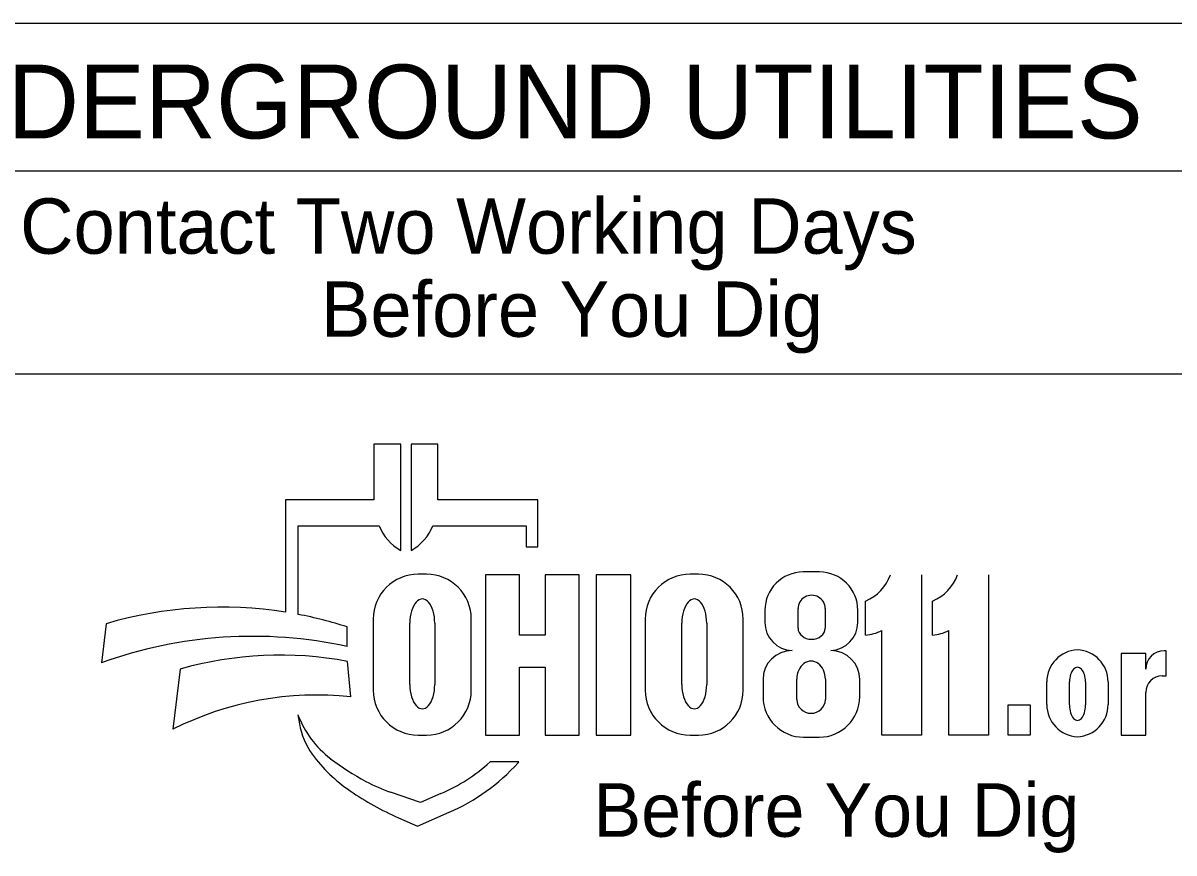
# Model space of a CAD drawing. Extents: x 0 to 34, y 0 to 22.
# Drawn here: x 27.662 to 31.093, y 12.841 to 15.314 of the extents above; entities that cross this region are included whole.
import ezdxf

# ---------------------------------------------------------------- set-up
doc = ezdxf.new("R2010")
doc.units = 0
doc.layers.add('SH_Data', color=7, linetype='Continuous')

msp = doc.modelspace()

# ---------------------------------------------------------------- linework, layer by layer
at = {"layer": 'SH_Data'}
for p, q in [((27.0189, 15.314), (32.2439, 15.314)), ((27.0189, 14.874), (32.2439, 14.874)), ((27.0189, 14.269), (32.2439, 14.269)), ((28.7879, 14.0595), (28.7078, 14.0595)), ((28.7078, 14.0595), (28.7078, 13.8929)), ((28.7879, 13.7427), (28.7879, 14.0595)), ((28.8991, 14.0595), (28.819, 14.0595)), ((28.819, 14.0595), (28.819, 13.7427)), ((28.8991, 13.8929), (28.8991, 14.0595)), ((28.7078, 13.8929), (28.4449, 13.8929)), ((28.4449, 13.8929), (28.4449, 13.5585)), ((29.1967, 13.8929), (28.8991, 13.8929)), ((29.1967, 13.7528), (29.1967, 13.8929)), ((28.4826, 13.5519), (28.4826, 13.8161)), ((28.4826, 13.8161), (28.7233, 13.8161)), ((28.8835, 13.8161), (29.1619, 13.8161)), ((29.1619, 13.8161), (29.1619, 13.7528)), ((29.1619, 13.7528), (29.1967, 13.7528)), ((28.8646, 13.6717), (28.8399, 13.6717)), ((29.1425, 13.6702), (29.041, 13.6702)), ((29.041, 13.6702), (29.041, 13.1923)), ((29.6753, 13.6717), (29.6506, 13.6717)), ((30.0365, 13.6783), (29.9876, 13.6783)), ((30.3402, 13.6702), (30.3402, 13.1923)), ((30.5403, 13.6702), (30.5403, 13.1923)), ((30.1735, 13.4899), (30.1735, 13.5918)), ((30.3736, 13.4899), (30.3736, 13.5918)), ((29.8736, 13.5643), (29.8736, 13.528)), ((29.9724, 13.511), (29.9724, 13.5697)), ((30.0533, 13.5697), (30.0533, 13.511)), ((30.1505, 13.528), (30.1505, 13.5643)), ((27.9098, 13.5243), (27.8958, 13.4076)), ((28.7062, 13.5381), (28.7062, 13.3259)), ((28.8151, 13.3429), (28.8151, 13.5257)), ((28.8895, 13.5257), (28.8895, 13.3429)), ((28.9982, 13.3259), (28.9982, 13.5381)), ((29.517, 13.5381), (29.517, 13.3259)), ((29.6259, 13.3429), (29.6259, 13.5257)), ((29.7003, 13.5257), (29.7003, 13.3429)), ((29.809, 13.3259), (29.809, 13.5381)), ((28.6288, 13.4566), (28.6288, 13.5146)), ((30.2217, 13.1923), (30.2217, 13.5039)), ((30.4219, 13.1923), (30.4219, 13.5039)), ((31.009, 13.4357), (30.936, 13.4357)), ((30.936, 13.4357), (30.936, 13.1923)), ((31.009, 13.3886), (31.009, 13.4357)), ((31.0697, 13.4434), (31.0638, 13.4434)), ((31.0697, 13.3689), (31.0697, 13.4434)), ((28.1305, 13.389), (28.1085, 13.2096)), ((28.6389, 13.3061), (28.6296, 13.4121)), ((29.1425, 13.1923), (29.1425, 13.3943)), ((29.868, 13.3578), (29.868, 13.307)), ((29.9688, 13.2981), (29.9688, 13.3592)), ((30.0538, 13.3592), (30.0538, 13.2981)), ((30.1565, 13.307), (30.1565, 13.3578)), ((30.7141, 13.2831), (30.7141, 13.3509)), ((30.7813, 13.282), (30.7813, 13.3509)), ((30.8294, 13.3509), (30.8294, 13.282)), ((30.8966, 13.3509), (30.8966, 13.2831)), ((31.0583, 13.3689), (31.0697, 13.3689)), ((31.009, 13.1923), (31.009, 13.3196)), ((28.4816, 13.2524), (28.4862, 13.2256)), ((28.8399, 13.1923), (28.8646, 13.1923)), ((29.041, 13.1923), (29.1425, 13.1923)), ((29.6506, 13.1923), (29.6753, 13.1923)), ((29.989, 13.1861), (30.0356, 13.1861)), ((30.3402, 13.1923), (30.2217, 13.1923)), ((30.5403, 13.1923), (30.4219, 13.1923)), ((30.936, 13.1923), (31.009, 13.1923)), ((29.1401, 13.1123), (29.0543, 13.1123)), ((29.1377, 13.1096), (29.1401, 13.1123)), ((28.8466, 12.9915), (28.7579, 13.0221)), ((28.9079, 13.0181), (28.8466, 12.9915)), ((28.7818, 12.9458), (28.8376, 12.9212)), ((28.8376, 12.9212), (28.9322, 12.9623))]:
    msp.add_line(p, q, dxfattribs=at)
for points in [[(29.1425, 13.3943), (29.2186, 13.3943), (29.2186, 13.1923), (29.3201, 13.1923), (29.3201, 13.6702), (29.2186, 13.6702), (29.2186, 13.4899), (29.1425, 13.4899), (29.1425, 13.6702)], [(29.3709, 13.1923), (29.4736, 13.1923), (29.4736, 13.6702), (29.3709, 13.6702), (29.3709, 13.1923)], [(29.9545, 13.4444), (29.9545, 13.4443)], [(30.07, 13.4443), (30.07, 13.4444)]]:
    msp.add_lwpolyline(points, dxfattribs=at)
msp.add_lwpolyline([(30.5983, 13.282), (30.6642, 13.282), (30.6642, 13.1923), (30.5983, 13.1923)], close=True, dxfattribs=at)
for centre, radius, start, end in [((28.8598, 13.871), 0.1471, 201.9296, 240.7469), ((28.7471, 13.871), 0.1471, 299.2531, 338.0704), ((28.8399, 13.5381), 0.1337, 90, 180), ((28.8646, 13.5381), 0.1337, 0, 90), ((29.6506, 13.5381), 0.1337, 90, 180), ((29.6753, 13.5381), 0.1337, 0, 90), ((29.9876, 13.5643), 0.114, 90, 180), ((30.0365, 13.5643), 0.114, 0, 90), ((30.1228, 13.7139), 0.1322, 292.5572, 340.7355), ((30.3229, 13.7139), 0.1322, 292.5572, 340.7355), ((28.2535, 12.35), 1.2235, 81.0007, 106.3144), ((28.2535, 12.35), 1.2235, 72.1402, 79.2074), ((29.9572, 13.528), 0.0837, 180, 268.1442), ((30.0668, 13.528), 0.0837, 272.2058, 0), ((28.3477, 12.1542), 1.3324, 77.8238, 109.8274), ((30.1615, 13.6216), 0.1322, 275.1733, 297.0931), ((30.3617, 13.6216), 0.1322, 275.1733, 297.0931), ((28.4291, 12.3369), 1.0937, 79.44, 105.8467), ((29.9545, 13.3578), 0.0865, 90, 180), ((30.07, 13.3578), 0.0865, 0, 90), ((30.8096, 13.3509), 0.0956, 92.5886, 180), ((30.801, 13.3509), 0.0956, 0, 87.4114), ((31.0638, 13.3886), 0.0548, 90, 180), ((31.0583, 13.3196), 0.0493, 90, 180), ((28.8399, 13.3259), 0.1337, 180, 270), ((28.8646, 13.3259), 0.1337, 270, 0), ((29.6506, 13.3259), 0.1337, 180, 270), ((29.6753, 13.3259), 0.1337, 270, 0), ((28.5367, 12.362), 0.9496, 83.8248, 116.8021), ((29.989, 13.307), 0.1209, 180, 270), ((30.0356, 13.307), 0.1209, 270, 0), ((30.8096, 13.2831), 0.0956, 180, 267.4114), ((30.801, 13.2831), 0.0956, 272.5886, 0), ((28.7616, 13.3601), 0.2999, 201.0457, 232.5314), ((28.6973, 13.2616), 0.2141, 189.6817, 216.0884), ((28.897, 13.4072), 0.4612, 216.0884, 235.7167), ((29.0492, 13.7354), 0.7728, 232.5314, 241.794), ((28.6937, 13.5117), 0.5381, 293.4582, 312.0712), ((28.6937, 13.5117), 0.599, 293.4582, 317.8286), ((28.922, 13.4981), 0.5035, 241.794, 250.9821), ((29.1457, 13.7721), 0.9028, 235.7167, 246.2325)]:
    msp.add_arc(centre, radius, start, end, dxfattribs=at)
for centre, major_axis, ratio, start_param, end_param in [((28.8523, 13.5257), (0, 0.0723), 0.514403, 4.712389, 7.853982), ((29.6631, 13.5257), (0, 0.0723), 0.514403, 4.712389, 7.853982), ((30.0128, 13.5697), (0.0404, 0), 0.969373, 0, 3.141593), ((30.0128, 13.511), (0.0404, 0), 0.818453, 3.141593, 6.283185), ((30.0113, 13.3592), (0, 0.0535), 0.794529, 4.712389, 7.853982), ((30.8053, 13.3509), (0, 0.0434), 0.553236, 4.712389, 7.853982), ((28.8523, 13.3429), (0, 0.0723), 0.514403, 1.570796, 4.712389), ((29.6631, 13.3429), (0, 0.0723), 0.514403, 1.570796, 4.712389), ((30.0113, 13.2981), (0.0425, 0), 0.959837, 3.141593, 6.283185), ((30.8053, 13.282), (0, 0.046), 0.522014, 1.570796, 4.712389)]:
    msp.add_ellipse(centre, major_axis=major_axis, ratio=ratio, start_param=start_param, end_param=end_param, dxfattribs=at)

# ---------------------------------------------------------------- texts
for s, height, p in [('UNDERGROUND UTILITIES', 0.22, (27.1915, 14.9701)), ('Contact Two Working Days', 0.165, (27.6533, 14.6266)), ('Before You Dig', 0.165, (28.5505, 14.3791)), ('Before You Dig', 0.15972, (29.3624, 12.8893))]:
    msp.add_text(s, height=height, dxfattribs=at).set_placement(p)

doc.saveas('drawing.dxf')
